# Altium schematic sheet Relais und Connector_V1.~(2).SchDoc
size A4; SheetNumber: 6; SheetTotal: 7
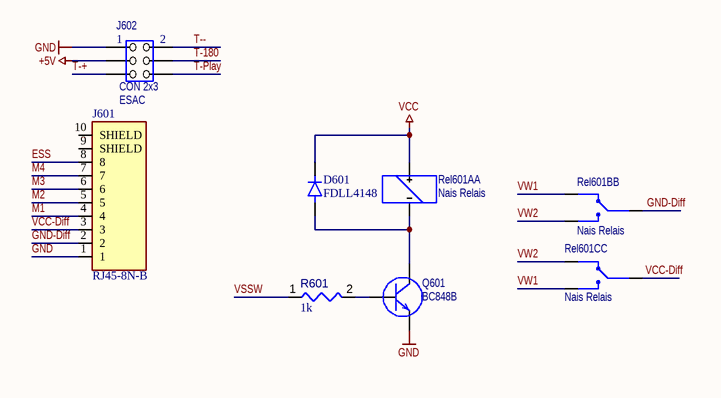
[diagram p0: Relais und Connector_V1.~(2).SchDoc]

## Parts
D601  FDLL4148  [DIOMELF3414N]
J601  RJ45-8N-B  [TE_RJ45-8N-B]
J602  CON 2x3  Use: ESAC  [J_2x3]
Q601  BC848B  [SOT-23]
R601  value 1k  [RESC1608X55X25ML10T15]  (hidden comment: Resistor 1k +/-1% 0603 100 mW)
Rel601A  Nais Relais  [Rel_THT_Nais]  (part A of 3)
Rel601B  Nais Relais  [Rel_THT_Nais]  (part B of 3)
Rel601C  Nais Relais  [Rel_THT_Nais]  (part C of 3)

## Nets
+5V: J602.3
GND: J601.1 J602.1 Q601.2(E)
VCC: D601.C Rel601A.5
ESS: J601.8
GND-Diff: J601.2 Rel601B.3
M1: J601.4
M2: J601.5
M3: J601.6
M4: J601.7
T-180: J602.4
T-+: J602.5
T--: J602.2
T-Play: J602.6
VCC-Diff: J601.3 Rel601C.6
VSSW: R601.1
VW1: Rel601B.2 Rel601C.8
VW2: Rel601B.1 Rel601C.7
NetD601_A: D601.A Q601.3(C) Rel601A.4
NetQ601_1: Q601.1(B) R601.2

Not connected (* = marked no-connect by the designer): J601 9(SHIELD) 10(SHIELD)

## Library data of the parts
D601 = FDLL4148: Diode Standard 100 V 200mA Surface Mount SOD-80; MF: ON Semiconductor
J601 = RJ45-8N-B: RJ Jack / Signal Line EMI/RFI Filters 6 TERM LOW PROFILE BLOCK INDUCTOR 8 PIN
J602 = J_THT_IDC 2x3: Stecker
Q601 = Q_SMD_NPN: NPN Transistor
R601 = CMP-009-00014-5: Chip Resistor, 1 KOhm, +/-1%, 0.1 W, -55 to 155 degC, 0603 (1608 Metric); Voltage Rating: 50V; Power: 100mW; Tolerance: 1%
Rel601A Rel601B Rel601C = Rel_THT_Nais: Nais DS2Y-S-DC12V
